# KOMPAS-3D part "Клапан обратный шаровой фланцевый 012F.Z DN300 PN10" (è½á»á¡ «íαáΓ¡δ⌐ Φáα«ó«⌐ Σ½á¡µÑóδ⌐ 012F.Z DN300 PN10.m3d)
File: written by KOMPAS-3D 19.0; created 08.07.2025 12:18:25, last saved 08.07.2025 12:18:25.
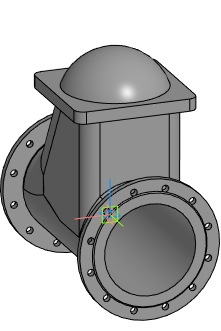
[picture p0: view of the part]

Document properties: Полное имя файла: E:\Dendor Работа Сачек\3D для проектировщиков\5.3 Тип 012F, 012F.Z Клапан обратный шаровой фланцевый\stp_Клапан обратный шаровой фланцевый 012F.Z PN10_16\Клапан обратный шаровой фланцевый 012F.Z DN300 PN10.m3d

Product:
- Part/product: Клапан обратный шаровой фланцевый 012F.Z DN300 PN10

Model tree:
1. Операция без истории:1  (labels: Клапан обратный шаровой фланцевый 012F.Z DN300 PN10)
